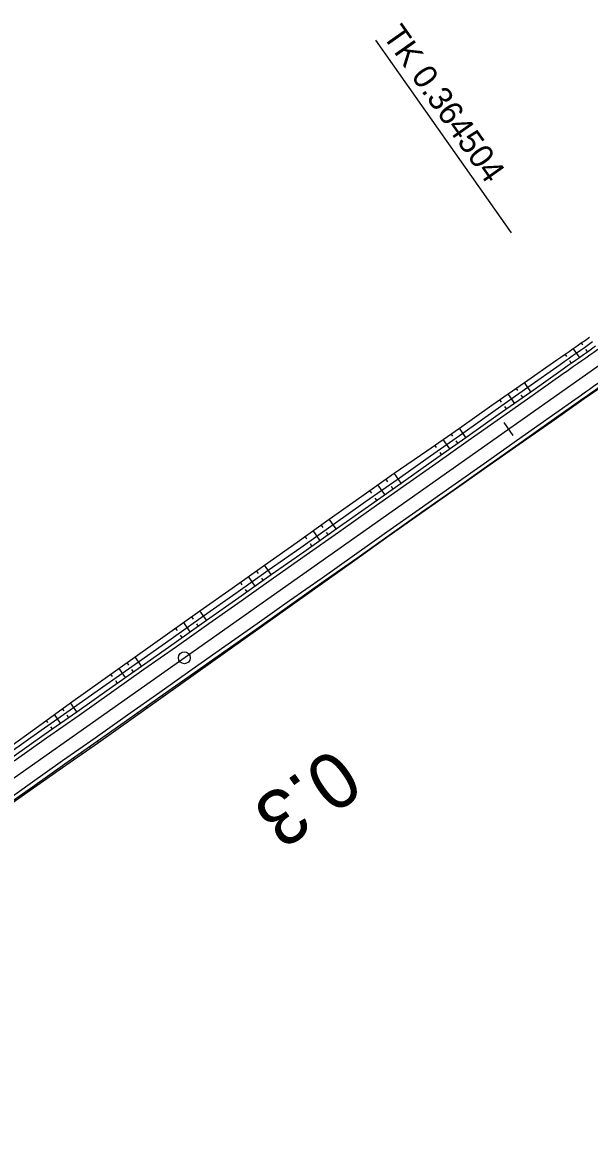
# Model space of a CAD drawing. Extents: x -481645 to -478728, y -1113199 to -1110710.
# Drawn here: x -480392.6 to -480321.2, y -1112820.8 to -1112678.9 of the extents above; entities that cross this region are included whole.
import ezdxf

# ---------------------------------------------------------------- set-up
doc = ezdxf.new("R2010")
doc.units = 0
for name, color, linetype in [('Vrstva 52', 7, 'Continuous'), ('Vrstva 53', 7, 'Continuous'), ('Vrstva 54', 7, 'Continuous'), ('Vrstva 55', 7, 'Continuous'), ('Vrstva 56', 7, 'Continuous'), ('Vrstva 57', 7, 'Continuous'), ('Vrstva 58', 7, 'Continuous'), ('Vrstva 59', 7, 'Continuous'), ('Vrstva 60', 7, 'Continuous'), ('Vrstva 61', 7, 'Continuous'), ('Vrstva 62', 7, 'Continuous')]:
    doc.layers.add(name, color=color, linetype=linetype)

msp = doc.modelspace()

# ---------------------------------------------------------------- linework, layer by layer
at = {"layer": 'Vrstva 52'}
msp.add_line((-480462.96, -1112822.86), (-480319.49, -1112721.76), dxfattribs=at)
at = {"layer": 'Vrstva 53'}
for p, q in [((-480329.36, -1112724.25), (-480325.25, -1112721.4)), ((-480333.46, -1112727.11), (-480329.36, -1112724.25)), ((-480337.55, -1112729.98), (-480333.46, -1112727.11)), ((-480325.91, -1112729.14), (-480321.81, -1112726.27)), ((-480341.66, -1112732.83), (-480337.55, -1112729.98)), ((-480330.01, -1112732.01), (-480325.91, -1112729.14)), ((-480345.77, -1112735.68), (-480341.66, -1112732.83)), ((-480334.1, -1112734.88), (-480330.01, -1112732.01)), ((-480349.86, -1112738.55), (-480345.77, -1112735.68)), ((-480338.2, -1112737.75), (-480334.1, -1112734.88)), ((-480353.94, -1112741.45), (-480349.86, -1112738.55)), ((-480342.29, -1112740.61), (-480338.2, -1112737.75)), ((-480358.01, -1112744.35), (-480353.94, -1112741.45)), ((-480346.38, -1112743.5), (-480342.29, -1112740.61)), ((-480362.09, -1112747.24), (-480358.01, -1112744.35)), ((-480350.45, -1112746.4), (-480346.38, -1112743.5)), ((-480366.17, -1112750.13), (-480362.09, -1112747.24)), ((-480354.52, -1112749.3), (-480350.45, -1112746.4)), ((-480370.25, -1112753.02), (-480366.17, -1112750.13)), ((-480358.6, -1112752.2), (-480354.52, -1112749.3)), ((-480374.33, -1112755.92), (-480370.25, -1112753.02)), ((-480362.67, -1112755.1), (-480358.6, -1112752.2)), ((-480366.74, -1112758), (-480362.67, -1112755.1)), ((-480378.41, -1112758.81), (-480374.33, -1112755.92)), ((-480370.82, -1112760.9), (-480366.74, -1112758)), ((-480382.48, -1112761.71), (-480378.41, -1112758.81)), ((-480374.89, -1112763.8), (-480370.82, -1112760.9)), ((-480386.55, -1112764.61), (-480382.48, -1112761.71)), ((-480378.96, -1112766.7), (-480374.89, -1112763.8)), ((-480390.61, -1112767.53), (-480386.55, -1112764.61)), ((-480383.04, -1112769.59), (-480378.96, -1112766.7)), ((-480394.66, -1112770.46), (-480390.61, -1112767.53)), ((-480387.14, -1112772.45), (-480383.04, -1112769.59)), ((-480391.24, -1112775.31), (-480387.14, -1112772.45)), ((-480395.34, -1112778.18), (-480391.24, -1112775.31))]:
    msp.add_line(p, q, dxfattribs=at)
for centre, radius, start, end in [((-481003.82, -1111744.76), 1189.24, 304.79128, 305.03196), ((-481012.18, -1111736.08), 1207.1, 304.88445, 305.12192)]:
    msp.add_arc(centre, radius, start, end, dxfattribs=at)
at = {"layer": 'Vrstva 54'}
for p, q in [((-480328.93, -1112724.85), (-480324.85, -1112721.97)), ((-480333.02, -1112727.73), (-480328.93, -1112724.85)), ((-480337.11, -1112730.61), (-480333.02, -1112727.73)), ((-480341.2, -1112733.49), (-480337.11, -1112730.61)), ((-480345.28, -1112736.37), (-480341.2, -1112733.49)), ((-480349.37, -1112739.25), (-480345.28, -1112736.37)), ((-480353.46, -1112742.13), (-480349.37, -1112739.25)), ((-480357.54, -1112745.01), (-480353.46, -1112742.13)), ((-480361.63, -1112747.89), (-480357.54, -1112745.01)), ((-480365.72, -1112750.77), (-480361.63, -1112747.89)), ((-480369.81, -1112753.65), (-480365.72, -1112750.77)), ((-480373.89, -1112756.53), (-480369.81, -1112753.65)), ((-480377.98, -1112759.41), (-480373.89, -1112756.53)), ((-480382.07, -1112762.29), (-480377.98, -1112759.41)), ((-480386.16, -1112765.17), (-480382.07, -1112762.29)), ((-480390.24, -1112768.05), (-480386.16, -1112765.17)), ((-480394.33, -1112770.93), (-480390.24, -1112768.05))]:
    msp.add_line(p, q, dxfattribs=at)
msp.add_arc((-481009.07, -1111746.82), 1191.25, 305.05551, 305.29583, dxfattribs=at)
at = {"layer": 'Vrstva 55'}
for p, q in [((-480328.55, -1112725.4), (-480324.46, -1112722.52)), ((-480332.64, -1112728.27), (-480328.55, -1112725.4)), ((-480325.96, -1112729.07), (-480321.87, -1112726.19)), ((-480336.73, -1112731.16), (-480332.64, -1112728.27)), ((-480330.05, -1112731.95), (-480325.96, -1112729.07)), ((-480340.81, -1112734.03), (-480336.73, -1112731.16)), ((-480334.13, -1112734.83), (-480330.05, -1112731.95)), ((-480344.9, -1112736.92), (-480340.81, -1112734.03)), ((-480338.22, -1112737.71), (-480334.13, -1112734.83)), ((-480348.99, -1112739.8), (-480344.9, -1112736.92)), ((-480342.31, -1112740.59), (-480338.22, -1112737.71)), ((-480353.07, -1112742.68), (-480348.99, -1112739.8)), ((-480346.4, -1112743.47), (-480342.31, -1112740.59)), ((-480357.16, -1112745.56), (-480353.07, -1112742.68)), ((-480350.48, -1112746.35), (-480346.4, -1112743.47)), ((-480361.25, -1112748.44), (-480357.16, -1112745.56)), ((-480354.57, -1112749.23), (-480350.48, -1112746.35)), ((-480365.34, -1112751.32), (-480361.25, -1112748.44)), ((-480358.66, -1112752.11), (-480354.57, -1112749.23)), ((-480369.42, -1112754.2), (-480365.34, -1112751.32)), ((-480362.74, -1112755), (-480358.66, -1112752.11)), ((-480373.51, -1112757.08), (-480369.42, -1112754.2)), ((-480366.83, -1112757.88), (-480362.74, -1112755)), ((-480377.6, -1112759.96), (-480373.51, -1112757.08)), ((-480370.92, -1112760.76), (-480366.83, -1112757.88)), ((-480381.68, -1112762.84), (-480377.6, -1112759.96)), ((-480375.01, -1112763.64), (-480370.92, -1112760.76)), ((-480385.77, -1112765.72), (-480381.68, -1112762.84)), ((-480379.09, -1112766.52), (-480375.01, -1112763.64)), ((-480389.86, -1112768.6), (-480385.77, -1112765.72)), ((-480383.18, -1112769.4), (-480379.09, -1112766.52)), ((-480393.95, -1112771.48), (-480389.86, -1112768.6)), ((-480387.27, -1112772.28), (-480383.18, -1112769.4)), ((-480391.35, -1112775.16), (-480387.27, -1112772.28)), ((-480395.44, -1112778.04), (-480391.35, -1112775.16))]:
    msp.add_line(p, q, dxfattribs=at)
for centre, radius, start, end in [((-481009.83, -1111745.73), 1193.25, 305.0557, 305.29565), ((-481015.02, -1111738.37), 1206.75, 305.05694, 305.29448)]:
    msp.add_arc(centre, radius, start, end, dxfattribs=at)
at = {"layer": 'Vrstva 56'}
for p, q in [((-480328.26, -1112725.8), (-480324.18, -1112722.92)), ((-480332.35, -1112728.68), (-480328.26, -1112725.8)), ((-480326.25, -1112728.66), (-480322.16, -1112725.78)), ((-480336.44, -1112731.56), (-480332.35, -1112728.68)), ((-480330.33, -1112731.54), (-480326.25, -1112728.66)), ((-480340.53, -1112734.44), (-480336.44, -1112731.56)), ((-480334.42, -1112734.43), (-480330.33, -1112731.54)), ((-480344.61, -1112737.32), (-480340.53, -1112734.44)), ((-480338.51, -1112737.3), (-480334.42, -1112734.43)), ((-480348.7, -1112740.2), (-480344.61, -1112737.32)), ((-480342.6, -1112740.19), (-480338.51, -1112737.3)), ((-480352.79, -1112743.08), (-480348.7, -1112740.2)), ((-480346.68, -1112743.06), (-480342.6, -1112740.19)), ((-480356.87, -1112745.97), (-480352.79, -1112743.08)), ((-480350.77, -1112745.95), (-480346.68, -1112743.06)), ((-480360.96, -1112748.84), (-480356.87, -1112745.97)), ((-480354.86, -1112748.83), (-480350.77, -1112745.95)), ((-480365.05, -1112751.73), (-480360.96, -1112748.84)), ((-480358.94, -1112751.71), (-480354.86, -1112748.83)), ((-480369.14, -1112754.6), (-480365.05, -1112751.73)), ((-480363.03, -1112754.59), (-480358.94, -1112751.71)), ((-480373.22, -1112757.49), (-480369.14, -1112754.6)), ((-480367.12, -1112757.47), (-480363.03, -1112754.59)), ((-480377.31, -1112760.37), (-480373.22, -1112757.49)), ((-480371.21, -1112760.35), (-480367.12, -1112757.47)), ((-480381.4, -1112763.25), (-480377.31, -1112760.37)), ((-480375.29, -1112763.23), (-480371.21, -1112760.35)), ((-480385.48, -1112766.13), (-480381.4, -1112763.25)), ((-480379.38, -1112766.11), (-480375.29, -1112763.23)), ((-480389.57, -1112769.01), (-480385.48, -1112766.13)), ((-480383.47, -1112768.99), (-480379.38, -1112766.11)), ((-480393.66, -1112771.89), (-480389.57, -1112769.01)), ((-480387.55, -1112771.87), (-480383.47, -1112768.99)), ((-480391.64, -1112774.75), (-480387.55, -1112771.87)), ((-480395.73, -1112777.63), (-480391.64, -1112774.75))]:
    msp.add_line(p, q, dxfattribs=at)
for centre, radius, start, end in [((-481010.41, -1111744.91), 1194.75, 305.05584, 305.29552), ((-481014.44, -1111739.19), 1205.25, 305.05681, 305.29461)]:
    msp.add_arc(centre, radius, start, end, dxfattribs=at)
at = {"layer": 'Vrstva 57'}
for p, q in [((-480328.26, -1112725.8), (-480324.18, -1112722.92)), ((-480332.35, -1112728.68), (-480328.26, -1112725.8)), ((-480326.25, -1112728.66), (-480322.16, -1112725.78)), ((-480336.44, -1112731.56), (-480332.35, -1112728.68)), ((-480330.33, -1112731.54), (-480326.25, -1112728.66)), ((-480340.53, -1112734.44), (-480336.44, -1112731.56)), ((-480334.42, -1112734.43), (-480330.33, -1112731.54)), ((-480344.61, -1112737.32), (-480340.53, -1112734.44)), ((-480338.51, -1112737.3), (-480334.42, -1112734.43)), ((-480348.7, -1112740.2), (-480344.61, -1112737.32)), ((-480342.6, -1112740.19), (-480338.51, -1112737.3)), ((-480352.79, -1112743.08), (-480348.7, -1112740.2)), ((-480346.68, -1112743.06), (-480342.6, -1112740.19)), ((-480356.87, -1112745.97), (-480352.79, -1112743.08)), ((-480350.77, -1112745.95), (-480346.68, -1112743.06)), ((-480360.96, -1112748.84), (-480356.87, -1112745.97)), ((-480354.86, -1112748.83), (-480350.77, -1112745.95)), ((-480365.05, -1112751.73), (-480360.96, -1112748.84)), ((-480358.94, -1112751.71), (-480354.86, -1112748.83)), ((-480369.14, -1112754.6), (-480365.05, -1112751.73)), ((-480363.03, -1112754.59), (-480358.94, -1112751.71)), ((-480373.22, -1112757.49), (-480369.14, -1112754.6)), ((-480367.12, -1112757.47), (-480363.03, -1112754.59)), ((-480377.31, -1112760.37), (-480373.22, -1112757.49)), ((-480371.21, -1112760.35), (-480367.12, -1112757.47)), ((-480381.4, -1112763.25), (-480377.31, -1112760.37)), ((-480375.29, -1112763.23), (-480371.21, -1112760.35)), ((-480385.48, -1112766.13), (-480381.4, -1112763.25)), ((-480379.38, -1112766.11), (-480375.29, -1112763.23)), ((-480389.57, -1112769.01), (-480385.48, -1112766.13)), ((-480383.47, -1112768.99), (-480379.38, -1112766.11)), ((-480393.66, -1112771.89), (-480389.57, -1112769.01)), ((-480387.55, -1112771.87), (-480383.47, -1112768.99)), ((-480391.64, -1112774.75), (-480387.55, -1112771.87)), ((-480395.73, -1112777.63), (-480391.64, -1112774.75))]:
    msp.add_line(p, q, dxfattribs=at)
for centre, radius, start, end in [((-481010.41, -1111744.91), 1194.75, 305.05584, 305.29552), ((-481014.44, -1111739.19), 1205.25, 305.05681, 305.29461)]:
    msp.add_arc(centre, radius, start, end, dxfattribs=at)
at = {"layer": 'Vrstva 58'}
msp.add_line((-480330.77, -1112730.93), (-480331.92, -1112729.3), dxfattribs=at)
at = {"layer": 'Vrstva 59'}
msp.add_line((-480348.12, -1112681.13), (-480331.01, -1112705.41), dxfattribs=at)
at = {"layer": 'Vrstva 60'}
msp.add_circle((-480372.21, -1112758.92), 0.75, dxfattribs=at)
at = {"layer": 'Vrstva 61'}
for p, q in [((-480322.42, -1112721.07), (-480323.2, -1112719.97)), ((-480321.98, -1112719.53), (-480322.17, -1112719.26)), ((-480321.4, -1112720.35), (-480321.59, -1112720.08)), ((-480324.02, -1112720.97), (-480324.22, -1112720.69)), ((-480323.44, -1112721.79), (-480323.63, -1112721.52)), ((-480328.55, -1112725.4), (-480329.36, -1112724.25)), ((-480330.6, -1112726.83), (-480331.41, -1112725.68)), ((-480330.17, -1112725.27), (-480330.38, -1112724.97)), ((-480329.57, -1112726.11), (-480329.77, -1112725.84)), ((-480332.22, -1112726.71), (-480332.43, -1112726.4)), ((-480331.62, -1112727.55), (-480331.81, -1112727.28)), ((-480336.73, -1112731.16), (-480337.55, -1112729.98)), ((-480338.77, -1112732.59), (-480339.61, -1112731.41)), ((-480338.36, -1112731.01), (-480338.58, -1112730.69)), ((-480337.75, -1112731.88), (-480337.94, -1112731.6)), ((-480340.41, -1112732.44), (-480340.64, -1112732.12)), ((-480339.79, -1112733.31), (-480339.98, -1112733.04)), ((-480344.9, -1112736.92), (-480345.77, -1112735.68)), ((-480346.94, -1112738.35), (-480347.82, -1112737.12)), ((-480346.55, -1112736.74), (-480346.79, -1112736.4)), ((-480345.92, -1112737.64), (-480346.11, -1112737.36)), ((-480348.59, -1112738.18), (-480348.84, -1112737.83)), ((-480347.97, -1112739.08), (-480348.16, -1112738.8)), ((-480353.07, -1112742.68), (-480353.94, -1112741.45)), ((-480355.12, -1112744.12), (-480355.97, -1112742.9)), ((-480354.72, -1112742.51), (-480354.96, -1112742.18)), ((-480354.1, -1112743.4), (-480354.29, -1112743.12)), ((-480356.76, -1112743.96), (-480356.99, -1112743.62)), ((-480356.14, -1112744.84), (-480356.33, -1112744.56)), ((-480361.25, -1112748.44), (-480362.09, -1112747.24)), ((-480363.29, -1112749.88), (-480364.13, -1112748.69)), ((-480362.88, -1112748.29), (-480363.11, -1112747.96)), ((-480364.92, -1112749.73), (-480365.15, -1112749.41)), ((-480362.27, -1112749.16), (-480362.46, -1112748.88)), ((-480364.31, -1112750.6), (-480364.51, -1112750.32)), ((-480369.42, -1112754.2), (-480370.25, -1112753.02)), ((-480371.47, -1112755.64), (-480372.29, -1112754.47)), ((-480371.05, -1112754.06), (-480371.27, -1112753.75)), ((-480373.09, -1112755.5), (-480373.31, -1112755.2)), ((-480370.44, -1112754.92), (-480370.64, -1112754.64)), ((-480372.49, -1112756.36), (-480372.68, -1112756.08)), ((-480379.21, -1112759.83), (-480379.42, -1112759.53)), ((-480377.6, -1112759.96), (-480378.41, -1112758.81)), ((-480381.25, -1112761.28), (-480381.46, -1112760.98)), ((-480379.64, -1112761.4), (-480380.44, -1112760.26)), ((-480378.62, -1112760.68), (-480378.81, -1112760.4)), ((-480380.66, -1112762.12), (-480380.85, -1112761.84)), ((-480387.37, -1112765.62), (-480387.57, -1112765.34)), ((-480385.77, -1112765.72), (-480386.55, -1112764.61)), ((-480389.41, -1112767.07), (-480389.59, -1112766.8)), ((-480387.82, -1112767.16), (-480388.58, -1112766.07)), ((-480386.79, -1112766.44), (-480386.98, -1112766.16)), ((-480388.84, -1112767.88), (-480389.03, -1112767.6))]:
    msp.add_line(p, q, dxfattribs=at)
at = {"layer": 'Vrstva 62'}
for p, q in [((-480326.98, -1112729.79), (-480326.96, -1112729.83)), ((-480326.93, -1112729.86), (-480326.93, -1112729.86)), ((-480325.96, -1112729.07), (-480325.91, -1112729.14)), ((-480329.03, -1112731.23), (-480329, -1112731.26)), ((-480328.98, -1112731.29), (-480328.98, -1112731.29)), ((-480328, -1112730.51), (-480327.96, -1112730.58)), ((-480335.16, -1112735.55), (-480335.14, -1112735.57)), ((-480335.13, -1112735.59), (-480335.13, -1112735.59)), ((-480334.13, -1112734.83), (-480334.1, -1112734.88)), ((-480337.2, -1112736.99), (-480337.19, -1112737.01)), ((-480337.17, -1112737.03), (-480337.17, -1112737.03)), ((-480336.18, -1112736.27), (-480336.15, -1112736.31)), ((-480343.33, -1112741.31), (-480343.32, -1112741.32)), ((-480343.31, -1112741.34), (-480343.31, -1112741.34)), ((-480342.31, -1112740.59), (-480342.29, -1112740.61)), ((-480345.37, -1112742.75), (-480345.36, -1112742.77)), ((-480345.35, -1112742.78), (-480345.35, -1112742.78)), ((-480344.35, -1112742.03), (-480344.33, -1112742.06)), ((-480351.5, -1112747.07), (-480351.49, -1112747.1)), ((-480351.47, -1112747.13), (-480351.47, -1112747.13)), ((-480350.48, -1112746.35), (-480350.45, -1112746.4)), ((-480353.55, -1112748.51), (-480353.53, -1112748.54)), ((-480353.5, -1112748.58), (-480353.5, -1112748.58)), ((-480352.53, -1112747.79), (-480352.48, -1112747.85)), ((-480359.68, -1112752.83), (-480359.65, -1112752.88)), ((-480359.61, -1112752.92), (-480359.61, -1112752.92)), ((-480358.66, -1112752.11), (-480358.6, -1112752.2)), ((-480361.72, -1112754.27), (-480361.69, -1112754.32)), ((-480361.65, -1112754.37), (-480361.65, -1112754.37)), ((-480360.7, -1112753.55), (-480360.63, -1112753.65)), ((-480367.85, -1112758.59), (-480367.81, -1112758.66)), ((-480367.76, -1112758.72), (-480367.76, -1112758.72)), ((-480366.83, -1112757.88), (-480366.74, -1112758)), ((-480369.9, -1112760.03), (-480369.85, -1112760.1)), ((-480369.8, -1112760.17), (-480369.8, -1112760.17)), ((-480368.87, -1112759.31), (-480368.78, -1112759.45)), ((-480376.03, -1112764.35), (-480375.97, -1112764.44)), ((-480375.01, -1112763.64), (-480374.89, -1112763.8)), ((-480378.07, -1112765.79), (-480378.01, -1112765.88)), ((-480377.05, -1112765.07), (-480376.93, -1112765.25)), ((-480375.91, -1112764.52), (-480375.91, -1112764.52)), ((-480377.94, -1112765.97), (-480377.94, -1112765.97)), ((-480383.18, -1112769.4), (-480383.04, -1112769.59)), ((-480385.22, -1112770.84), (-480385.09, -1112771.02)), ((-480384.2, -1112770.12), (-480384.13, -1112770.21)), ((-480384.06, -1112770.31), (-480384.06, -1112770.31)), ((-480386.24, -1112771.56), (-480386.18, -1112771.65)), ((-480386.11, -1112771.74), (-480386.11, -1112771.74)), ((-480391.35, -1112775.16), (-480391.24, -1112775.31)), ((-480392.38, -1112775.88), (-480392.32, -1112775.95)), ((-480392.27, -1112776.03), (-480392.27, -1112776.03))]:
    msp.add_line(p, q, dxfattribs=at)

# ---------------------------------------------------------------- texts
at = {"layer": 'Vrstva 59'}
msp.add_text('TK 0.364504', height=2.999, rotation=305.1722, dxfattribs=at).set_placement((-480347.3, -1112680.56))
at = {"layer": 'Vrstva 60'}
msp.add_text('0.3', height=7, rotation=215.1265, dxfattribs=at).set_placement((-480353.3, -1112770.06))

doc.saveas('drawing.dxf')
